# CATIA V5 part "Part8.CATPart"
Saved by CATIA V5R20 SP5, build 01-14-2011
Part number: Part1
Bounding box of the stored display mesh (mm): x -100 to 100, y -99.999 to 99.999, z -2.5 to 19.843
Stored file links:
  E:\scc\Part8.CATPart
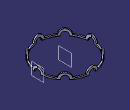
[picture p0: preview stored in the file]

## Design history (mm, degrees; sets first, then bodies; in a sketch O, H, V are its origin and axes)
Body1 (main body)
  Sketch1 on xy-plane, origin (0, 0, 0), H (1, 0, 0), V (0, 1, 0)
    circle A1 centre (0, 0) radius 100
  Pad1: profile Sketch1, direction (0, 0, 1), length 2.5, mirrored extent, thin wall 5
  Body2
    Sketch2 on xy-plane, origin (0, 0, 0), H (1, 0, 0), V (0, 1, 0)
      axis line L1 (97.5, 40) -> (97.5, -50)
      arc A1 centre (97.5, 0) radius 20 from (97.5, -20) to (97.5, 20) ccw
      point P4 (97.5, 20)
      point P5 (97.5, -20)
      distance O L1 = 97.5
      radius A1 = 20
      vertical: L1 V
      coincidence: L1 P4, L1 P5
    Shaft1: profile Sketch2, axis Sketch2.L1, angle 360
    CircPattern1: of Shaft1, instances 8, angular step 45, axis from face of Pad1
    Sketch3 on xy-plane, origin (0, 0, 0), H (1, 0, 0), V (0, 1, 0)
      circle A1 centre (0, 0) radius 95
      radius A1 = 95
    Pocket1: profile Sketch3, direction (0, 0, -1), length 60, mirrored extent
    Split1: SplitPlane start face of Pad1
    Sketch4 on xy-plane, origin (0, 0, 0), H (1, 0, 0), V (0, 1, 0)
      circle A1 centre (0, 0) radius 100
      radius A1 = 100
    Pocket2: profile Sketch4, direction (0, 0, -1), length 60, mirrored extent, outer side
  Assemble1: tool Body2
  Body3
    Plane1: type Offset, RefPlane yz-plane, Offset 97.5
    Sketch5 on Plane1, origin (97.5, 0, 0), H (0, 1, 0), V (0, 0, 1)
      arc A1 centre (0, 0) radius 12 from (-12, 0) to (12, 0) ccw
      axis line L1 (-20, 0) -> (20, 0)
      point P1 (-20, 0)
      point P3 (-12, 0)
      point P4 (12, 0)
      radius A1 = 12
      coincidence: P1 H, L1 P4, L1 P3
      horizontal: L1 H
    Shaft2: profile Sketch5, axis Sketch5.L1, angle 360
    CircPattern2: of Shaft2, instances 8, angular step 45, axis from face of Pad1
  Remove1: tool Body3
